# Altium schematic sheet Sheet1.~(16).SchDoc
size A3; SheetNumber: 1; SheetTotal: 2
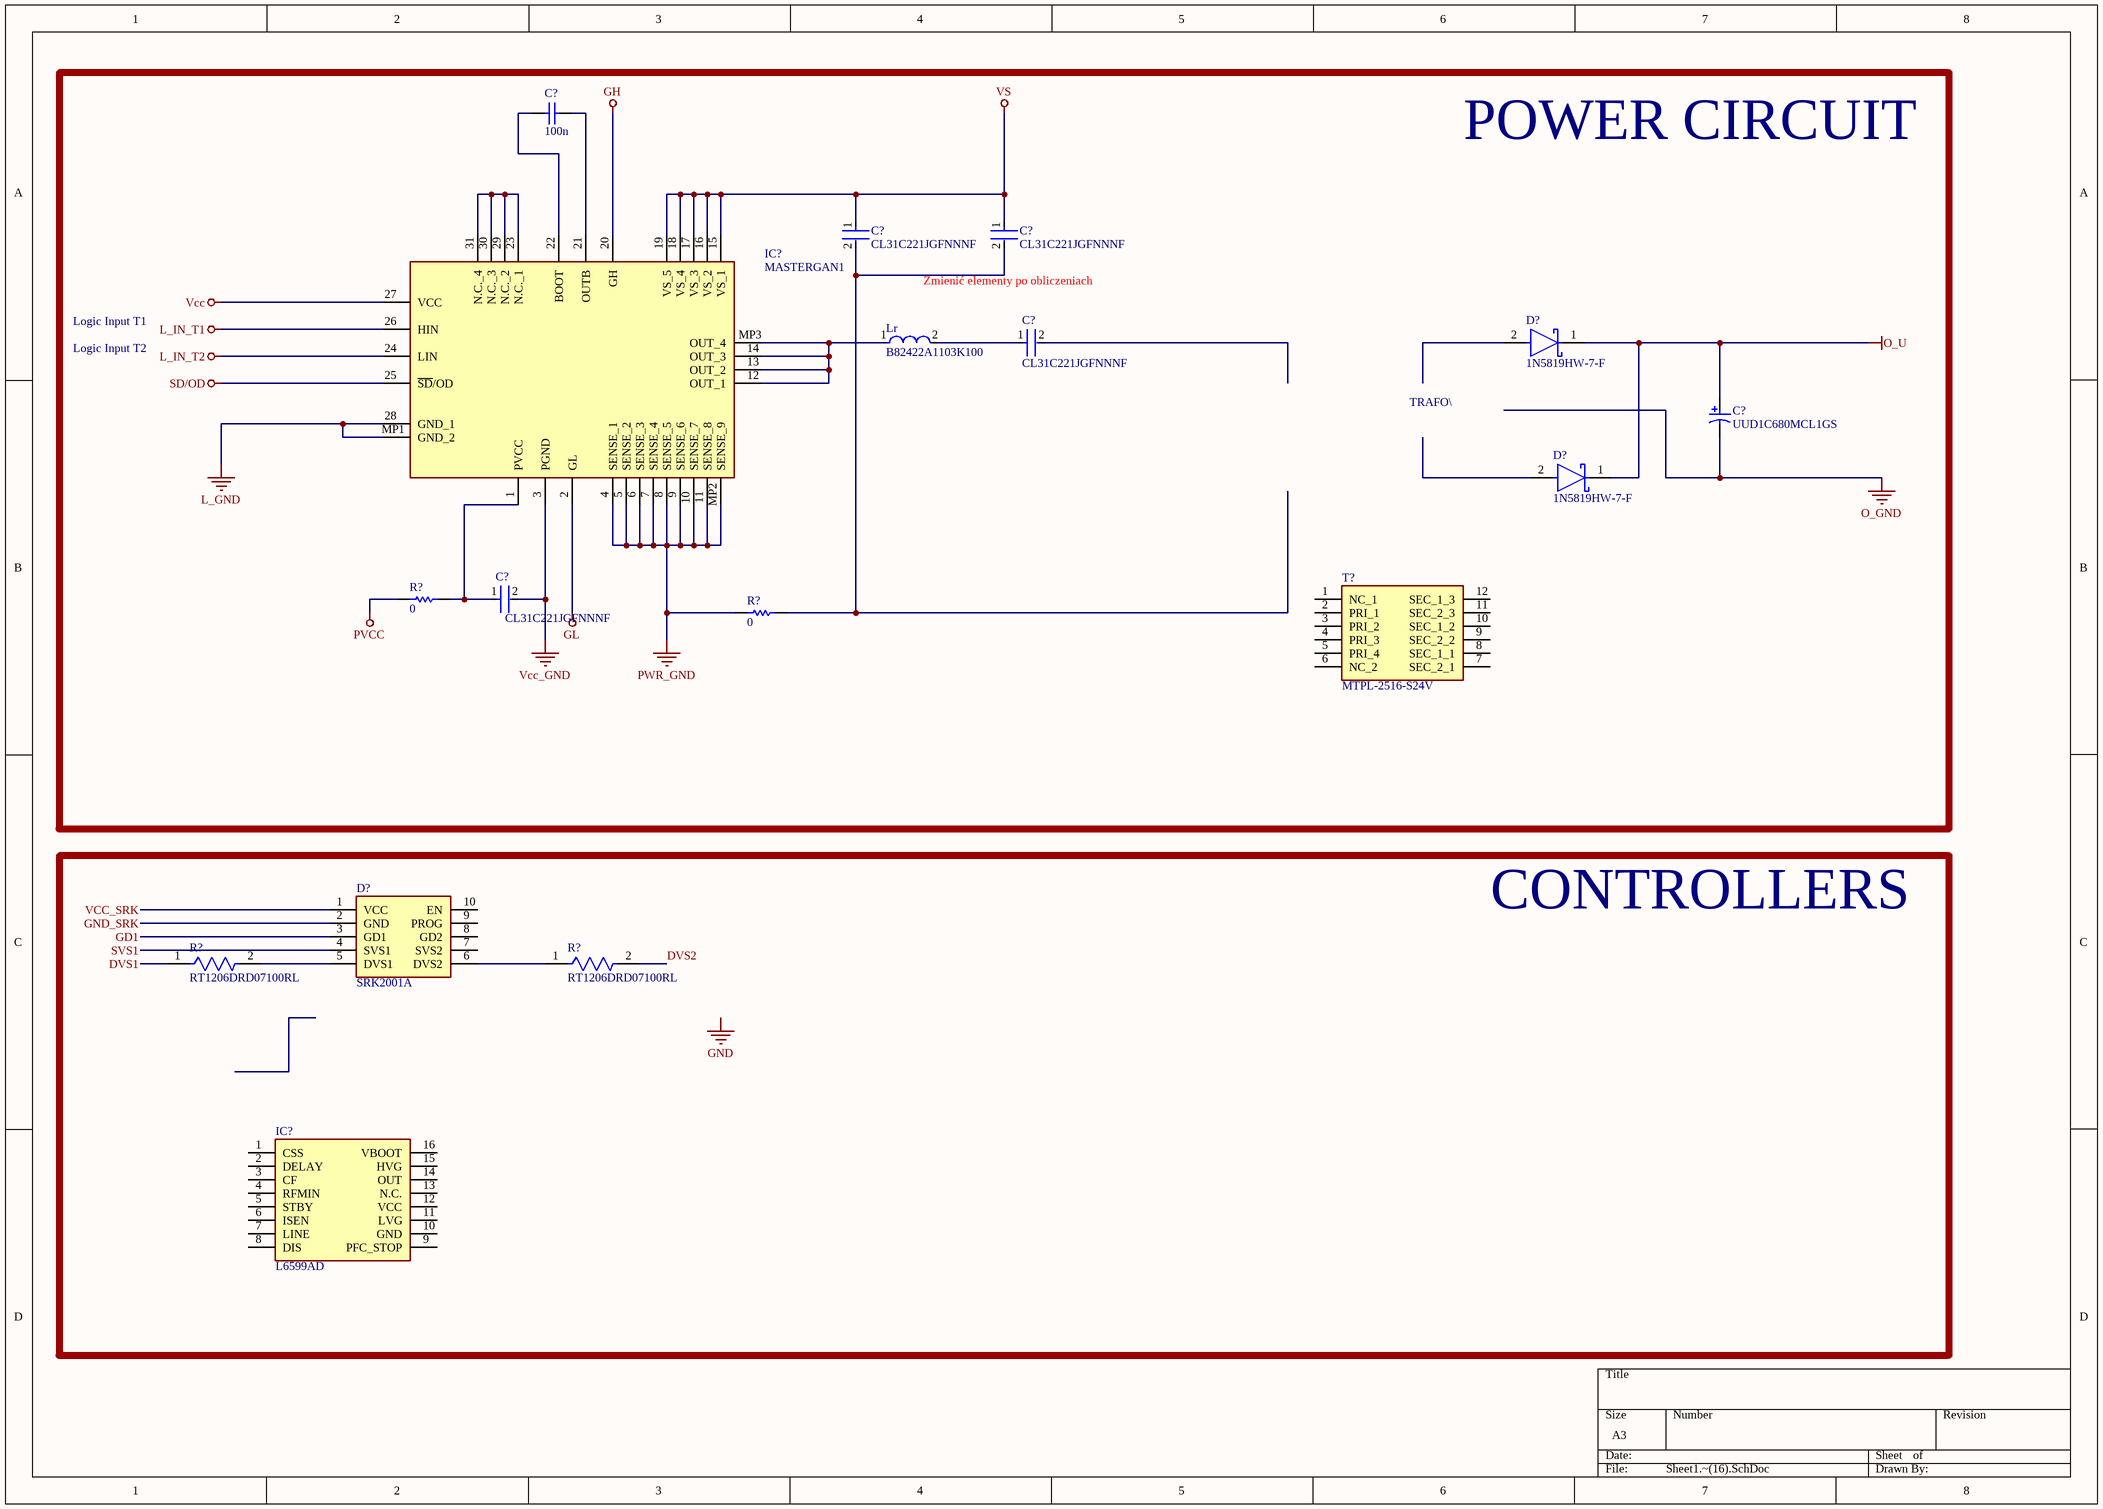
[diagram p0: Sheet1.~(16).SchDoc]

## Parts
(Parts that share a designator on the sheet are numbered #1, #2 ... from top to bottom, then left to right.)
C?#1  value 100n  (hidden comment: Capacitor)
C?#2  CL31C221JGFNNNF  [FP-CL31-IPC_C]
C?#3  CL31C221JGFNNNF  [FP-CL31-IPC_C]
C?#4  CL31C221JGFNNNF  [FP-CL31-IPC_C]
C?#5  UUD1C680MCL1GS  [NIC-CAPA2-6.3X5.8_V]
C?#6  CL31C221JGFNNNF  [FP-CL31-IPC_C]
D?#1  1N5819HW-7-F  [FP-SOD123-IPC_A]
D?#2  1N5819HW-7-F  [FP-SOD123-IPC_A]
D?#3  SRK2001A  [SOIC127P600X175-8N]
IC?#1  MASTERGAN1  [MASTERGAN1]
IC?#2  L6599AD  [SOIC127P600X175-16N]
Lr  B82422A1103K100  [FP-B82422A-MFG]
R?#1  value 0  (hidden comment: Resistor)
R?#2  value 0  (hidden comment: Resistor)
R?#3  RT1206DRD07100RL  [FP-RT1206-MFG]
R?#4  RT1206DRD07100RL  [FP-RT1206-MFG]
T?  MTPL-2516-S24V  [MTPL2516S24V]

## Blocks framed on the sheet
POWER CIRCUIT: C?#1-C?#6 D?#1 D?#2 IC?#1 Lr R?#1 R?#2 T?
CONTROLLERS: D?#3 IC?#2 R?#3 R?#4

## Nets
GH: IC?#1.20(GH)
GL: IC?#1.2(GL)
L_GND: IC?#1.28(GND_1) IC?#1.MP1(GND_2)
L_IN_T1: IC?#1.26(HIN)
L_IN_T2: IC?#1.24(LIN)
O_GND: C?#5.2
O_U: C?#5.1 D?#1.1(C) D?#2.1(C)
PVCC: R?#1.1
PWR_GND: IC?#1.4(SENSE_1) IC?#1.5(SENSE_2) IC?#1.6(SENSE_3) IC?#1.7(SENSE_4) IC?#1.8(SENSE_5) IC?#1.9(SENSE_6) IC?#1.10(SENSE_7) IC?#1.11(SENSE_8) IC?#1.MP2(SENSE_9) R?#2.1
SD/OD: IC?#1.25(~{SD}/OD)
Vcc: IC?#1.27(VCC)
Vcc_GND: C?#6.2 IC?#1.3(PGND)
VS: C?#2.1 C?#3.1 IC?#1.15(VS_1) IC?#1.16(VS_2) IC?#1.17(VS_3) IC?#1.18(VS_4) IC?#1.19(VS_5)
DVS1: R?#3.1
DVS2: R?#4.2
GD1: D?#3.3(GD1)
GND_SRK: D?#3.2(GND)
SVS1: D?#3.4(SVS1)
VCC_SRK: D?#3.1(VCC)
NetC?#1_1: C?#1.1 IC?#1.22(BOOT)
NetC?#1_2: C?#1.2 IC?#1.21(OUTB)
NetC?#2_2: C?#2.2 C?#3.2 R?#2.2
NetC?#4_1: C?#4.1 Lr.2
NetC?#6_1: C?#6.1 IC?#1.1(PVCC) R?#1.2
NetD?#3_5: D?#3.5(DVS1) R?#3.2
NetD?#3_6: D?#3.6(DVS2) R?#4.1
NetIC?#1_12: IC?#1.12(OUT_1) IC?#1.13(OUT_2) IC?#1.14(OUT_3) IC?#1.MP3(OUT_4) Lr.1
NetIC?#1_23: IC?#1.23(N.C._1) IC?#1.29(N.C._2) IC?#1.30(N.C._3) IC?#1.31(N.C._4)

Not connected (* = marked no-connect by the designer): C?#4 2; D?#1 2(A); D?#2 2(A); D?#3 7(SVS2) 8(GD2) 9(PROG) 10(EN); IC?#2 1(CSS) 2(DELAY) 3(CF) 4(RFMIN) 5(STBY) 6(ISEN) 7(LINE) 8(DIS) 9(PFC_STOP) 10(GND) 11(LVG) 12(VCC) 13(N.C.) 14(OUT) 15(HVG) 16(VBOOT); T? 1(NC_1) 2(PRI_1) 3(PRI_2) 4(PRI_3) 5(PRI_4) 6(NC_2) 7(SEC_2_1) 8(SEC_1_1) 9(SEC_2_2) 10(SEC_1_2) 11(SEC_2_3) 12(SEC_1_3)

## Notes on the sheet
- Zmienić elementy po obliczeniach
- Logic Input T1
- Logic Input T2
- TRAFO\
- Labels drawn without touching a wire or pin: GND

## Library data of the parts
C?#1 = Capacitor: SimulationGenericComponent: True
C?#2-C?#4 C?#6 = CMP-13271-001211-1: Cap Ceramic 220pF 500V C0G ±5% SMD 1206 +125°C Embossed T/R
C?#5 = CMP-0687-00035-1: Aluminum Electrolytic Capacitor, UD Series, Low Impedance, 68 uF, 16 V, + / - 20%, -55 to 105 degC, Chip Type, 6.3 x 5.8 mm D x L, Pb-Free, Reel; Manufacturer: Nichicon; Rated Voltage: 16 V; Endurance Time: 2000 h; Rated Ripple Current (at 100kHz): 230 mA; Rated Capacitance: 68 uF; Impedance: 0.44 Ohm; Packing: Dia382mm Reel; Tolerance Rated Capacitance: -20 to 20%
D?#1 D?#2 = CMP-0303-00003-3: DIODE SCHOTTKY 40V 1A SOD123; Forward Voltage: 450mV; Capacitance: 110pF; Max Forward Surge Current (Ifsm): 25A; Peak Reverse Current: 50uA; Polarity: Standard; Element Configuration: Single; Max Power Dissipation: 450mW
D?#3 = SRK2001A: Diode; Manufacturer_Name: STMicroelectronics
IC?#1 = MASTERGAN1: Integrated Circuit; Manufacturer_Name: STMicroelectronics
IC?#2 = L6599AD: Integrated Circuit; Manufacturer_Name: STMicroelectronics
Lr = CMP-2000-05912-2: FIXED IND 10UH 180MA 1.6 OHM SMD; Tolerance: 10%; Core Material: Ferrite; Q Factor: 27; Self Resonant Frequency: 25MHz; Shielding: Unshielded; Test Frequency: 1MHz; Series Resistance: 1.6R
R?#1 R?#2 = Resistor: SimulationGenericComponent: True
R?#3 R?#4 = CMP-03412-027315-1: RES 100 OHM 1/4W .5% SMD 1206; Manufacturer: Yageo; Voltage Rating: 200V; Resistance: 100Ω; Description: RT1206 100Ω 0.25W 25 ppm/°C 0.01%; Power Rating: 0.25W; Value: 100Ω; Temperature Coefficient: 25 ppm/°C; Tolerance: 0.0001
T? = MTPL-2516-S24V: Transformer; Manufacturer_Name: Vishay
